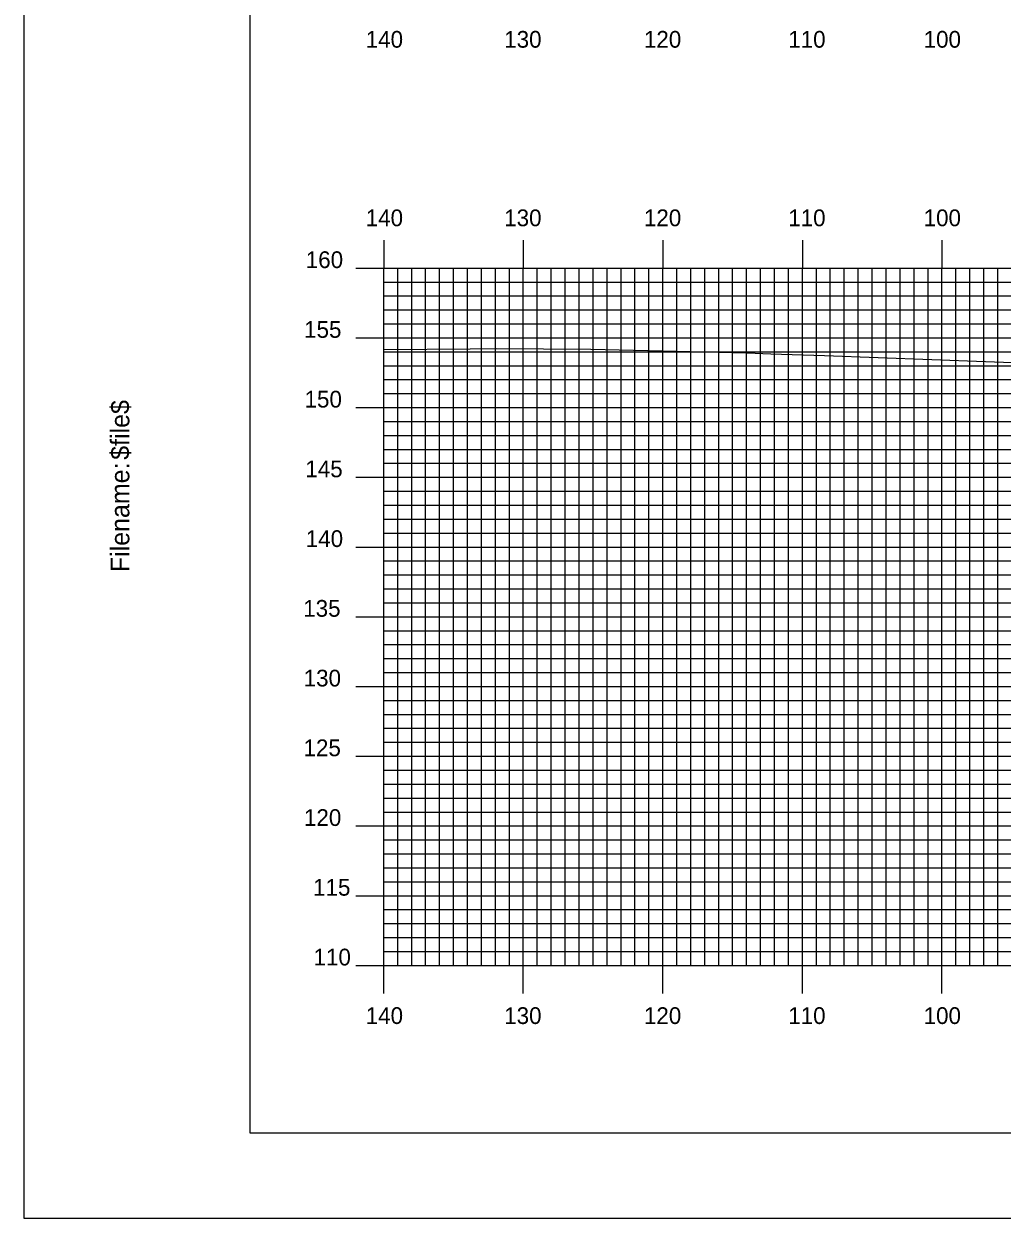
# Model space of a CAD drawing. Extents: x 1770448 to 1770792, y 442591 to 442811.
# Drawn here: x 1770448.3 to 1770518.3, y 442590.5 to 442676.2 of the extents above; entities that cross this region are included whole.
import ezdxf

# ---------------------------------------------------------------- set-up
doc = ezdxf.new("R2010")
doc.units = 0
for name, color, linetype in [('BORDER', 7, 'Continuous'), ('H_V ANNOTATION', 7, 'Continuous'), ('MAJOR', 7, 'Continuous'), ('MINOR', 7, 'Continuous'), ('PLOT BOUNDARY', 7, 'Continuous'), ('S_Roadway_Centerline', 7, 'Continuous')]:
    doc.layers.add(name, color=color, linetype=linetype)

msp = doc.modelspace()

# ---------------------------------------------------------------- linework, layer by layer
at = {"layer": 'BORDER'}
msp.add_lwpolyline([(1770464.441, 442596.665), (1770784.441, 442596.665), (1770784.441, 442806.665), (1770464.441, 442806.665)], close=True, dxfattribs=at)
at = {"layer": 'MAJOR'}
for p, q in [((1770474.041, 442660.669), (1770474.041, 442658.665)), ((1770484.041, 442660.669), (1770484.041, 442658.665)), ((1770494.041, 442660.669), (1770494.041, 442658.665)), ((1770504.041, 442660.669), (1770504.041, 442658.665)), ((1770514.041, 442660.669), (1770514.041, 442658.665)), ((1770472.037, 442658.665), (1770474.041, 442658.665)), ((1770474.041, 442658.665), (1770754.041, 442658.665)), ((1770474.041, 442608.665), (1770474.041, 442658.665)), ((1770474.041, 442608.665), (1770474.041, 442658.665)), ((1770474.041, 442658.665), (1770754.041, 442658.665)), ((1770484.041, 442608.665), (1770484.041, 442658.665)), ((1770494.041, 442608.665), (1770494.041, 442658.665)), ((1770504.041, 442608.665), (1770504.041, 442658.665)), ((1770514.041, 442608.665), (1770514.041, 442658.665)), ((1770472.037, 442653.665), (1770474.041, 442653.665)), ((1770474.041, 442653.665), (1770754.041, 442653.665)), ((1770472.037, 442648.665), (1770474.041, 442648.665)), ((1770474.041, 442648.665), (1770754.041, 442648.665)), ((1770472.037, 442643.665), (1770474.041, 442643.665)), ((1770474.041, 442643.665), (1770754.041, 442643.665)), ((1770472.037, 442638.665), (1770474.041, 442638.665)), ((1770474.041, 442638.665), (1770754.041, 442638.665)), ((1770472.037, 442633.665), (1770474.041, 442633.665)), ((1770474.041, 442633.665), (1770754.041, 442633.665)), ((1770472.037, 442628.665), (1770474.041, 442628.665)), ((1770474.041, 442628.665), (1770754.041, 442628.665)), ((1770472.037, 442623.665), (1770474.041, 442623.665)), ((1770474.041, 442623.665), (1770754.041, 442623.665)), ((1770472.037, 442618.665), (1770474.041, 442618.665)), ((1770474.041, 442618.665), (1770754.041, 442618.665)), ((1770472.037, 442613.665), (1770474.041, 442613.665)), ((1770474.041, 442613.665), (1770754.041, 442613.665)), ((1770472.037, 442608.665), (1770474.041, 442608.665)), ((1770474.041, 442608.665), (1770754.041, 442608.665)), ((1770474.041, 442608.665), (1770754.041, 442608.665)), ((1770474.041, 442606.661), (1770474.041, 442608.665)), ((1770484.041, 442606.661), (1770484.041, 442608.665)), ((1770494.041, 442606.661), (1770494.041, 442608.665)), ((1770504.041, 442606.661), (1770504.041, 442608.665)), ((1770514.041, 442606.661), (1770514.041, 442608.665))]:
    msp.add_line(p, q, dxfattribs=at)
at = {"layer": 'MINOR'}
for p, q in [((1770475.041, 442608.665), (1770475.041, 442658.665)), ((1770476.041, 442608.665), (1770476.041, 442658.665)), ((1770477.041, 442608.665), (1770477.041, 442658.665)), ((1770478.041, 442608.665), (1770478.041, 442658.665)), ((1770479.041, 442608.665), (1770479.041, 442658.665)), ((1770480.041, 442608.665), (1770480.041, 442658.665)), ((1770481.041, 442608.665), (1770481.041, 442658.665)), ((1770482.041, 442608.665), (1770482.041, 442658.665)), ((1770483.041, 442608.665), (1770483.041, 442658.665)), ((1770485.041, 442608.665), (1770485.041, 442658.665)), ((1770486.041, 442608.665), (1770486.041, 442658.665)), ((1770487.041, 442608.665), (1770487.041, 442658.665)), ((1770488.041, 442608.665), (1770488.041, 442658.665)), ((1770489.041, 442608.665), (1770489.041, 442658.665)), ((1770490.041, 442608.665), (1770490.041, 442658.665)), ((1770491.041, 442608.665), (1770491.041, 442658.665)), ((1770492.041, 442608.665), (1770492.041, 442658.665)), ((1770493.041, 442608.665), (1770493.041, 442658.665)), ((1770495.041, 442608.665), (1770495.041, 442658.665)), ((1770496.041, 442608.665), (1770496.041, 442658.665)), ((1770497.041, 442608.665), (1770497.041, 442658.665)), ((1770498.041, 442608.665), (1770498.041, 442658.665)), ((1770499.041, 442608.665), (1770499.041, 442658.665)), ((1770500.041, 442608.665), (1770500.041, 442658.665)), ((1770501.041, 442608.665), (1770501.041, 442658.665)), ((1770502.041, 442608.665), (1770502.041, 442658.665)), ((1770503.041, 442608.665), (1770503.041, 442658.665)), ((1770505.041, 442608.665), (1770505.041, 442658.665)), ((1770506.041, 442608.665), (1770506.041, 442658.665)), ((1770507.041, 442608.665), (1770507.041, 442658.665)), ((1770508.041, 442608.665), (1770508.041, 442658.665)), ((1770509.041, 442608.665), (1770509.041, 442658.665)), ((1770510.041, 442608.665), (1770510.041, 442658.665)), ((1770511.041, 442608.665), (1770511.041, 442658.665)), ((1770512.041, 442608.665), (1770512.041, 442658.665)), ((1770513.041, 442608.665), (1770513.041, 442658.665)), ((1770515.041, 442608.665), (1770515.041, 442658.665)), ((1770516.041, 442608.665), (1770516.041, 442658.665)), ((1770517.041, 442608.665), (1770517.041, 442658.665)), ((1770518.041, 442608.665), (1770518.041, 442658.665)), ((1770474.041, 442657.665), (1770754.041, 442657.665)), ((1770474.041, 442657.665), (1770476.045, 442657.665)), ((1770474.041, 442656.665), (1770754.041, 442656.665)), ((1770474.041, 442656.665), (1770476.045, 442656.665)), ((1770474.041, 442655.665), (1770754.041, 442655.665)), ((1770474.041, 442655.665), (1770476.045, 442655.665)), ((1770474.041, 442654.665), (1770754.041, 442654.665)), ((1770474.041, 442654.665), (1770476.045, 442654.665)), ((1770474.041, 442652.665), (1770754.041, 442652.665)), ((1770474.041, 442652.665), (1770476.045, 442652.665)), ((1770474.041, 442651.665), (1770754.041, 442651.665)), ((1770474.041, 442651.665), (1770476.045, 442651.665)), ((1770474.041, 442650.665), (1770754.041, 442650.665)), ((1770474.041, 442650.665), (1770476.045, 442650.665)), ((1770474.041, 442649.665), (1770754.041, 442649.665)), ((1770474.041, 442649.665), (1770476.045, 442649.665)), ((1770474.041, 442647.665), (1770754.041, 442647.665)), ((1770474.041, 442647.665), (1770476.045, 442647.665)), ((1770474.041, 442646.665), (1770754.041, 442646.665)), ((1770474.041, 442646.665), (1770476.045, 442646.665)), ((1770474.041, 442645.665), (1770754.041, 442645.665)), ((1770474.041, 442645.665), (1770476.045, 442645.665)), ((1770474.041, 442644.665), (1770754.041, 442644.665)), ((1770474.041, 442644.665), (1770476.045, 442644.665)), ((1770474.041, 442642.665), (1770754.041, 442642.665)), ((1770474.041, 442642.665), (1770476.045, 442642.665)), ((1770474.041, 442641.665), (1770754.041, 442641.665)), ((1770474.041, 442641.665), (1770476.045, 442641.665)), ((1770474.041, 442640.665), (1770754.041, 442640.665)), ((1770474.041, 442640.665), (1770476.045, 442640.665)), ((1770474.041, 442639.665), (1770754.041, 442639.665)), ((1770474.041, 442639.665), (1770476.045, 442639.665)), ((1770474.041, 442637.665), (1770754.041, 442637.665)), ((1770474.041, 442637.665), (1770476.045, 442637.665)), ((1770474.041, 442636.665), (1770754.041, 442636.665)), ((1770474.041, 442636.665), (1770476.045, 442636.665)), ((1770474.041, 442635.665), (1770754.041, 442635.665)), ((1770474.041, 442635.665), (1770476.045, 442635.665)), ((1770474.041, 442634.665), (1770754.041, 442634.665)), ((1770474.041, 442634.665), (1770476.045, 442634.665)), ((1770474.041, 442632.665), (1770754.041, 442632.665)), ((1770474.041, 442632.665), (1770476.045, 442632.665)), ((1770474.041, 442631.665), (1770754.041, 442631.665)), ((1770474.041, 442631.665), (1770476.045, 442631.665)), ((1770474.041, 442630.665), (1770754.041, 442630.665)), ((1770474.041, 442630.665), (1770476.045, 442630.665)), ((1770474.041, 442629.665), (1770754.041, 442629.665)), ((1770474.041, 442629.665), (1770476.045, 442629.665)), ((1770474.041, 442627.665), (1770754.041, 442627.665)), ((1770474.041, 442627.665), (1770476.045, 442627.665)), ((1770474.041, 442626.665), (1770754.041, 442626.665)), ((1770474.041, 442626.665), (1770476.045, 442626.665)), ((1770474.041, 442625.665), (1770754.041, 442625.665)), ((1770474.041, 442625.665), (1770476.045, 442625.665)), ((1770474.041, 442624.665), (1770754.041, 442624.665)), ((1770474.041, 442624.665), (1770476.045, 442624.665)), ((1770474.041, 442622.665), (1770754.041, 442622.665)), ((1770474.041, 442622.665), (1770476.045, 442622.665)), ((1770474.041, 442621.665), (1770754.041, 442621.665)), ((1770474.041, 442621.665), (1770476.045, 442621.665)), ((1770474.041, 442620.665), (1770754.041, 442620.665)), ((1770474.041, 442620.665), (1770476.045, 442620.665)), ((1770474.041, 442619.665), (1770754.041, 442619.665)), ((1770474.041, 442619.665), (1770476.045, 442619.665)), ((1770474.041, 442617.665), (1770754.041, 442617.665)), ((1770474.041, 442617.665), (1770476.045, 442617.665)), ((1770474.041, 442616.665), (1770754.041, 442616.665)), ((1770474.041, 442616.665), (1770476.045, 442616.665)), ((1770474.041, 442615.665), (1770754.041, 442615.665)), ((1770474.041, 442615.665), (1770476.045, 442615.665)), ((1770474.041, 442614.665), (1770754.041, 442614.665)), ((1770474.041, 442614.665), (1770476.045, 442614.665)), ((1770474.041, 442612.665), (1770754.041, 442612.665)), ((1770474.041, 442612.665), (1770476.045, 442612.665)), ((1770474.041, 442611.665), (1770754.041, 442611.665)), ((1770474.041, 442611.665), (1770476.045, 442611.665)), ((1770474.041, 442610.665), (1770754.041, 442610.665)), ((1770474.041, 442610.665), (1770476.045, 442610.665)), ((1770474.041, 442609.665), (1770754.041, 442609.665)), ((1770474.041, 442609.665), (1770476.045, 442609.665))]:
    msp.add_line(p, q, dxfattribs=at)
at = {"layer": 'PLOT BOUNDARY'}
msp.add_lwpolyline([(1770448.254, 442590.547), (1770788.254, 442590.547), (1770788.254, 442810.547), (1770448.254, 442810.547)], close=True, dxfattribs=at)
at = {"layer": 'S_Roadway_Centerline'}
msp.add_lwpolyline([(1770474.041, 442652.821), (1770480.242, 442652.875), (1770482.089, 442652.902), (1770488.882, 442652.851), (1770500.075, 442652.584), (1770501.784, 442652.524), (1770505.624, 442652.39), (1770521.011, 442651.825), (1770523.955, 442651.605), (1770528.346, 442651.404), (1770536.61, 442650.868), (1770541.267, 442650.887), (1770560.703, 442649.56), (1770560.709, 442649.559), (1770572.501, 442648.868), (1770580.263, 442648.266), (1770589.826, 442647.784), (1770599.917, 442647.161), (1770608.957, 442646.389), (1770619.82, 442645.879), (1770622.677, 442645.714), (1770639.496, 442644.896), (1770644.071, 442644.564), (1770651.96, 442644.146)], dxfattribs=at)

# ---------------------------------------------------------------- texts
at = {"layer": 'BORDER'}
for s, p in [('$file$', (1770455.811, 442644.916)), ('Filename:', (1770455.811, 442636.862))]:
    msp.add_text(s, height=1.3392, rotation=90, dxfattribs=at).set_placement(p)
at = {"layer": 'H_V ANNOTATION'}
for s, p in [('140', (1770472.746, 442674.465)), ('130', (1770482.671, 442674.465)), ('120', (1770492.682, 442674.465)), ('110', (1770503.024, 442674.465)), ('100', (1770512.725, 442674.465)), ('140', (1770472.746, 442661.665)), ('130', (1770482.671, 442661.665)), ('120', (1770492.682, 442661.665)), ('110', (1770503.024, 442661.665)), ('100', (1770512.725, 442661.665)), ('160', (1770468.451, 442658.665)), ('155', (1770468.333, 442653.665)), ('150', (1770468.365, 442648.665)), ('145', (1770468.419, 442643.665)), ('140', (1770468.451, 442638.665)), ('135', (1770468.269, 442633.665)), ('130', (1770468.301, 442628.665)), ('125', (1770468.29, 442623.665)), ('120', (1770468.322, 442618.665)), ('115', (1770468.976, 442613.665)), ('110', (1770469.008, 442608.665)), ('140', (1770472.746, 442604.465)), ('130', (1770482.671, 442604.465)), ('120', (1770492.682, 442604.465)), ('110', (1770503.024, 442604.465)), ('100', (1770512.725, 442604.465))]:
    msp.add_text(s, height=1.2, dxfattribs=at).set_placement(p)
at = {"layer": 'MAJOR'}
msp.add_text('-', height=0.012, dxfattribs=at).set_placement((1770474.032, 442608.665))

doc.saveas('drawing.dxf')
